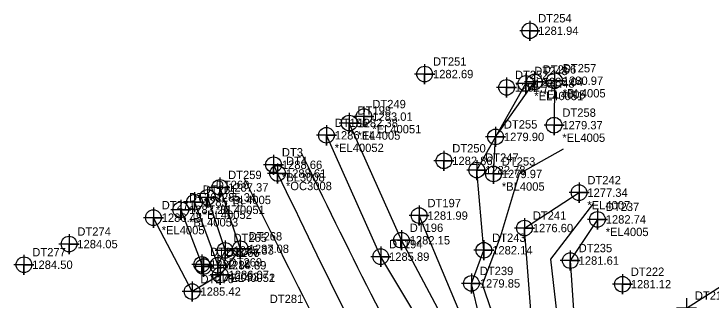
# Model space of a CAD drawing. Extents: x 1394009 to 1394411, y 957864 to 958364.
# Drawn here: x 1394009 to 1394217.7, y 958278.5 to 958364.2 of the extents above; entities that cross this region are included whole.
import ezdxf

# ---------------------------------------------------------------- set-up
doc = ezdxf.new("R2010")
doc.units = 0
for name, color, linetype in [('Exist DTM Breakline', 7, 'Continuous'), ('Exist DTM Breakline Cogo Comment', 7, 'Continuous'), ('Exist DTM Breakline Cogo Elevation', 7, 'Continuous'), ('Exist DTM Breakline Cogo Number', 7, 'Continuous'), ('Exist DTM Breakline Cogo Point CELL', 7, 'Continuous'), ('Exist DTM Breakline Underwater', 7, 'Continuous'), ('Exist DTM Breakline Underwater Cogo Comment', 7, 'Continuous'), ('Exist DTM Breakline Underwater Cogo Elevation', 7, 'Continuous'), ('Exist DTM Breakline Underwater Cogo Number', 7, 'Continuous'), ('Exist DTM Breakline Underwater Cogo Point CELL', 7, 'Continuous'), ('Exist DTM Crownline', 7, 'Continuous'), ('Exist DTM Regular Point Cogo Elevation', 7, 'Continuous'), ('Exist Hydro Stream or Body of Water', 7, 'Continuous'), ('Exist Roads EOP', 7, 'Continuous'), ('Exist Structure Minor Culvert Topo', 7, 'Continuous'), ('Exist Structure Minor Culvert Topo Terminator', 7, 'Continuous'), ('Exist Structure Minor Footbridge', 7, 'Continuous'), ('Exist Structure Minor Footbridge Terminator', 7, 'Continuous'), ('PH Exist DTM NCFMP LIDAR Elevation Point', 7, 'Continuous'), ('Raster_Level_0', 7, 'Continuous')]:
    doc.layers.add(name, color=color, linetype=linetype)

msp = doc.modelspace()

# ---------------------------------------------------------------- linework, layer by layer
at = {"layer": 'Exist DTM Breakline'}
for p, q in [((1394170.8481, 958344.1785), (1394170.7186, 958330.8718)), ((1394063.042, 958307.812), (1394069.9899, 958288.935)), ((1394058.9162, 958305.5481), (1394065.2064, 958289.1828))]:
    msp.add_line(p, q, dxfattribs=at)
for points in [[(1394242.4363, 958236.4587), (1394250.3213, 958249.8392), (1394247.4683, 958258.6227), (1394226.1736, 958256.7484), (1394200.4578, 958246.4971), (1394175.9465, 958237.5482), (1394166.0162, 958243.1539), (1394150.9651, 958262.3435), (1394145.9876, 958283.4911), (1394149.6991, 958293.4183), (1394147.595, 958317.4165), (1394162.2974, 958343.3573)], [(1394153.8085, 958328.2238), (1394164.8354, 958343.8094)], [(1394201.5002, 958152.1258), (1394182.2949, 958191.1856), (1394144.2973, 958260.2559), (1394124.9997, 958296.4083), (1394109.3726, 958331.5215)], [(1394190.4005, 958148.8159), (1394191.5413, 958156.6052), (1394176.0985, 958186.3137), (1394153.7403, 958228.0077), (1394140.0661, 958255.9875), (1394118.8047, 958291.5046), (1394102.5433, 958327.8357)], [(1394152.5846, 958316.2619), (1394153.1879, 958327.1812)], [(1394070.6172, 958312.2397), (1394076.7621, 958293.8578), (1394070.7535, 958286.0492), (1394062.3328, 958281.0618), (1394050.726, 958303.1803)], [(1394066.9181, 958309.2642), (1394072.2129, 958293.3836), (1394069.9934, 958288.9301)], [(1394203.3254, 958156.4773), (1394188.2939, 958197.0575), (1394161.6676, 958234.367), (1394146.9232, 958264.2671), (1394130.3208, 958303.8046)], [(1394183.7059, 958302.6672), (1394175.5913, 958290.3266), (1394176.7902, 958272.6343), (1394192.7029, 958271.0839), (1394210.3962, 958276.1116), (1394227.7375, 958287.1282), (1394241.3942, 958284.8435), (1394266.8472, 958274.7526), (1394273.951, 958265.5798), (1394280.4133, 958252.6154), (1394279.4205, 958214.8325), (1394286.3541, 958194.8367), (1394283.5006, 958151.7161)]]:
    msp.add_lwpolyline(points, dxfattribs=at)
at = {"layer": 'Exist DTM Breakline Cogo Point CELL'}
for points in [[(1394162.2974, 958346.3573), (1394162.2974, 958340.3573), (1394162.2974, 958343.3573), (1394165.2974, 958343.3573), (1394159.2974, 958343.3573)], [(1394164.8354, 958346.8094), (1394164.8354, 958340.8094), (1394164.8354, 958343.8094), (1394167.8354, 958343.8094), (1394161.8354, 958343.8094)], [(1394170.8481, 958347.1785), (1394170.8481, 958341.1785), (1394170.8481, 958344.1785), (1394173.8481, 958344.1785), (1394167.8481, 958344.1785)], [(1394113.7962, 958336.4391), (1394113.7962, 958330.4391), (1394113.7962, 958333.4391), (1394116.7962, 958333.4391), (1394110.7962, 958333.4391)], [(1394109.3726, 958334.5215), (1394109.3726, 958328.5215), (1394109.3726, 958331.5215), (1394112.3726, 958331.5215), (1394106.3726, 958331.5215)], [(1394170.7186, 958333.8718), (1394170.7186, 958327.8718), (1394170.7186, 958330.8718), (1394173.7186, 958330.8718), (1394167.7186, 958330.8718)], [(1394102.5433, 958330.8357), (1394102.5433, 958324.8357), (1394102.5433, 958327.8357), (1394105.5433, 958327.8357), (1394099.5433, 958327.8357)], [(1394153.1978, 958330.3606), (1394153.1978, 958324.3606), (1394153.1978, 958327.3606), (1394156.1978, 958327.3606), (1394150.1978, 958327.3606)], [(1394147.595, 958320.4165), (1394147.595, 958314.4165), (1394147.595, 958317.4165), (1394150.595, 958317.4165), (1394144.595, 958317.4165)], [(1394152.5846, 958319.2619), (1394152.5846, 958313.2619), (1394152.5846, 958316.2619), (1394155.5846, 958316.2619), (1394149.5846, 958316.2619)], [(1394070.6172, 958315.2397), (1394070.6172, 958309.2397), (1394070.6172, 958312.2397), (1394073.6172, 958312.2397), (1394067.6172, 958312.2397)], [(1394066.9181, 958312.2642), (1394066.9181, 958306.2642), (1394066.9181, 958309.2642), (1394069.9181, 958309.2642), (1394063.9181, 958309.2642)], [(1394063.042, 958310.812), (1394063.042, 958304.812), (1394063.042, 958307.812), (1394066.042, 958307.812), (1394060.042, 958307.812)], [(1394058.9162, 958308.5481), (1394058.9162, 958302.5481), (1394058.9162, 958305.5481), (1394061.9162, 958305.5481), (1394055.9162, 958305.5481)], [(1394050.726, 958306.1803), (1394050.726, 958300.1803), (1394050.726, 958303.1803), (1394053.726, 958303.1803), (1394047.726, 958303.1803)], [(1394130.3208, 958306.8046), (1394130.3208, 958300.8046), (1394130.3208, 958303.8046), (1394133.3208, 958303.8046), (1394127.3208, 958303.8046)], [(1394183.7059, 958305.6672), (1394183.7059, 958299.6672), (1394183.7059, 958302.6672), (1394186.7059, 958302.6672), (1394180.7059, 958302.6672)], [(1394124.9997, 958299.4083), (1394124.9997, 958293.4083), (1394124.9997, 958296.4083), (1394127.9997, 958296.4083), (1394121.9997, 958296.4083)], [(1394072.2129, 958296.3836), (1394072.2129, 958290.3836), (1394072.2129, 958293.3836), (1394075.2129, 958293.3836), (1394069.2129, 958293.3836)], [(1394076.7621, 958296.8578), (1394076.7621, 958290.8578), (1394076.7621, 958293.8578), (1394079.7621, 958293.8578), (1394073.7621, 958293.8578)], [(1394149.6991, 958296.4183), (1394149.6991, 958290.4183), (1394149.6991, 958293.4183), (1394152.6991, 958293.4183), (1394146.6991, 958293.4183)], [(1394118.8047, 958294.5046), (1394118.8047, 958288.5046), (1394118.8047, 958291.5046), (1394121.8047, 958291.5046), (1394115.8047, 958291.5046)], [(1394175.5913, 958293.3266), (1394175.5913, 958287.3266), (1394175.5913, 958290.3266), (1394178.5913, 958290.3266), (1394172.5913, 958290.3266)], [(1394065.2064, 958292.1828), (1394065.2064, 958286.1828), (1394065.2064, 958289.1828), (1394068.2064, 958289.1828), (1394062.2064, 958289.1828)], [(1394069.9899, 958291.935), (1394069.9899, 958285.935), (1394069.9899, 958288.935), (1394072.9899, 958288.935), (1394066.9899, 958288.935)], [(1394069.9934, 958291.9301), (1394069.9934, 958285.9301), (1394069.9934, 958288.9301), (1394072.9934, 958288.9301), (1394066.9934, 958288.9301)], [(1394070.7535, 958289.0492), (1394070.7535, 958283.0492), (1394070.7535, 958286.0492), (1394073.7535, 958286.0492), (1394067.7535, 958286.0492)], [(1394145.9876, 958286.4911), (1394145.9876, 958280.4911), (1394145.9876, 958283.4911), (1394148.9876, 958283.4911), (1394142.9876, 958283.4911)], [(1394062.3328, 958284.0618), (1394062.3328, 958278.0618), (1394062.3328, 958281.0618), (1394065.3328, 958281.0618), (1394059.3328, 958281.0618)], [(1394210.3962, 958279.1116), (1394210.3962, 958273.1116), (1394210.3962, 958276.1116), (1394213.3962, 958276.1116), (1394207.3962, 958276.1116)]]:
    msp.add_lwpolyline(points, dxfattribs=at)
for centre in [(1394162.2974, 958343.3573), (1394164.8354, 958343.8094), (1394170.8481, 958344.1785), (1394113.7962, 958333.4391), (1394109.3726, 958331.5215), (1394170.7186, 958330.8718), (1394102.5433, 958327.8357), (1394153.1978, 958327.3606), (1394147.595, 958317.4165), (1394152.5846, 958316.2619), (1394070.6172, 958312.2397), (1394063.042, 958307.812), (1394066.9181, 958309.2642), (1394058.9162, 958305.5481), (1394130.3208, 958303.8046), (1394050.726, 958303.1803), (1394183.7059, 958302.6672), (1394124.9997, 958296.4083), (1394072.2129, 958293.3836), (1394076.7621, 958293.8578), (1394149.6991, 958293.4183), (1394118.8047, 958291.5046), (1394065.2064, 958289.1828), (1394069.9899, 958288.935), (1394069.9934, 958288.9301), (1394175.5913, 958290.3266), (1394070.7535, 958286.0492), (1394145.9876, 958283.4911), (1394062.3328, 958281.0618)]:
    msp.add_circle(centre, 2.344, dxfattribs=at)
at = {"layer": 'Exist DTM Breakline Underwater'}
msp.add_lwpolyline([(1394229.3063, 958094.7507), (1394267.6222, 958126.159), (1394273.9153, 958153.4417), (1394270.8807, 958172.7151), (1394257.7841, 958202.8194), (1394247.0365, 958219.368), (1394259.7999, 958250.0935), (1394260.5275, 958261.5147), (1394243.0302, 958273.0023), (1394215.1121, 958260.9873), (1394175.4465, 958249.379), (1394164.3967, 958267.5944), (1394161.8631, 958300.0699), (1394178.2103, 958310.6665)], dxfattribs=at)
at = {"layer": 'Exist DTM Breakline Underwater Cogo Point CELL'}
for points in [[(1394178.2103, 958313.6665), (1394178.2103, 958307.6665), (1394178.2103, 958310.6665), (1394181.2103, 958310.6665), (1394175.2103, 958310.6665)], [(1394161.8631, 958303.0699), (1394161.8631, 958297.0699), (1394161.8631, 958300.0699), (1394164.8631, 958300.0699), (1394158.8631, 958300.0699)]]:
    msp.add_lwpolyline(points, dxfattribs=at)
for centre in [(1394178.2103, 958310.6665), (1394161.8631, 958300.0699)]:
    msp.add_circle(centre, 2.344, dxfattribs=at)
at = {"layer": 'Exist DTM Crownline'}
msp.add_line((1394086.7137, 958319.0127), (1394087.9321, 958316.4176), dxfattribs=at)
msp.add_spline([(1394087.9321, 958316.4176), (1394109.0623, 958273.1922), (1394131.7594, 958230.1822), (1394152.5248, 958192.8438), (1394173.9492, 958155.4634)], degree=3, dxfattribs=at)
at = {"layer": 'Exist Hydro Stream or Body of Water'}
for points in [[(1394221.231, 958104.5797), (1394238.8971, 958116.0346), (1394254.7004, 958129.0614), (1394261.0998, 958155.6228), (1394258.5223, 958177.5159), (1394245.4045, 958205.4301), (1394241.5211, 958222.9502), (1394246.6022, 958237.6666), (1394253.5489, 958252.431), (1394251.9663, 958257.7082), (1394245.398, 958262.4184), (1394226.1093, 958259.8812), (1394198.4822, 958248.5108), (1394177.4215, 958243.2011), (1394168.9777, 958246.0581), (1394155.8669, 958264.1507), (1394149.2709, 958283.1502), (1394154.661, 958297.4554), (1394160.3871, 958316.4078), (1394173.556, 958323.8378)], [(1394231.5705, 958091.2594), (1394270.5171, 958123.5077), (1394277.8383, 958154.0025), (1394278.608, 958197.1243), (1394267.0972, 958226.2539), (1394275.5986, 958257.1902), (1394265.6306, 958269.8313), (1394243.4303, 958275.2121), (1394210.2309, 958270.0539), (1394177.5999, 958260.6264), (1394172.1027, 958270.6648), (1394169.7578, 958290.7959), (1394182.6519, 958307.5361)]]:
    msp.add_lwpolyline(points, dxfattribs=at)
at = {"layer": 'Exist Roads EOP'}
for p, q in [((1394094.8972, 958322.8354), (1394096.2145, 958320.2223)), ((1394077.957, 958314.8579), (1394078.897, 958312.8974))]:
    msp.add_line(p, q, dxfattribs=at)
for points in [[(1394096.2145, 958320.2223), (1394117.2204, 958277.6897), (1394140.0936, 958234.4745), (1394160.6957, 958197.1466), (1394182.7363, 958159.1242)], [(1394078.897, 958312.8974), (1394101.0229, 958268.6968), (1394123.3315, 958225.72), (1394144.2526, 958188.5895), (1394165.818, 958150.9033)]]:
    msp.add_spline(points, degree=3, dxfattribs=at)
at = {"layer": 'Exist Structure Minor Culvert Topo Terminator'}
for points in [[(1394086.7137, 958322.0127), (1394086.7137, 958316.0127), (1394086.7137, 958319.0127), (1394089.7137, 958319.0127), (1394083.7137, 958319.0127)], [(1394087.9321, 958319.4176), (1394087.9321, 958313.4176), (1394087.9321, 958316.4176), (1394090.9321, 958316.4176), (1394084.9321, 958316.4176)]]:
    msp.add_lwpolyline(points, dxfattribs=at)
for centre in [(1394086.7137, 958319.0127), (1394087.9321, 958316.4176)]:
    msp.add_circle(centre, 2.344, dxfattribs=at)
at = {"layer": 'PH Exist DTM NCFMP LIDAR Elevation Point'}
for points in [[(1394163.4711, 958362.1342), (1394163.4711, 958356.1342), (1394163.4711, 958359.1342), (1394166.4711, 958359.1342), (1394160.4711, 958359.1342)], [(1394131.9735, 958349.1769), (1394131.9735, 958343.1769), (1394131.9735, 958346.1769), (1394134.9735, 958346.1769), (1394128.9735, 958346.1769)], [(1394156.5103, 958345.175), (1394156.5103, 958339.175), (1394156.5103, 958342.175), (1394159.5103, 958342.175), (1394153.5103, 958342.175)], [(1394137.7358, 958323.1974), (1394137.7358, 958317.1974), (1394137.7358, 958320.1974), (1394140.7358, 958320.1974), (1394134.7358, 958320.1974)], [(1394025.4625, 958298.2779), (1394025.4625, 958292.2779), (1394025.4625, 958295.2779), (1394028.4625, 958295.2779), (1394022.4625, 958295.2779)], [(1394011.9701, 958292.0925), (1394011.9701, 958286.0925), (1394011.9701, 958289.0925), (1394014.9701, 958289.0925), (1394008.9701, 958289.0925)], [(1394065.7235, 958291.5141), (1394065.7235, 958285.5141), (1394065.7235, 958288.5141), (1394068.7235, 958288.5141), (1394062.7235, 958288.5141)], [(1394191.2134, 958286.2551), (1394191.2134, 958280.2551), (1394191.2134, 958283.2551), (1394194.2134, 958283.2551), (1394188.2134, 958283.2551)]]:
    msp.add_lwpolyline(points, dxfattribs=at)
for centre in [(1394163.4711, 958359.1342), (1394131.9735, 958346.1769), (1394156.5103, 958342.175), (1394137.7358, 958320.1974), (1394025.4625, 958295.2779), (1394011.9701, 958289.0925), (1394065.7235, 958288.5141), (1394191.2134, 958283.2551)]:
    msp.add_circle(centre, 2.344, dxfattribs=at)

# ---------------------------------------------------------------- texts
at = {"layer": 'Exist DTM Breakline Cogo Comment'}
for s, p in [('*EL4005', (1394167.3354, 958338.8094)), ('*BL4005', (1394173.3481, 958339.1785)), ('*EL40051', (1394164.7974, 958338.3573)), ('*EL40051', (1394116.2962, 958328.4391)), ('*EL4005', (1394111.8726, 958326.5215)), ('*EL4005', (1394173.2186, 958325.8718)), ('*EL40052', (1394105.0433, 958322.8357)), ('*BL4005', (1394155.0846, 958311.2619)), ('*BL4005', (1394073.1172, 958307.2397)), ('*BL40051', (1394069.4181, 958304.2642)), ('*BL40052', (1394065.542, 958302.812)), ('*BL40053', (1394061.4162, 958300.5481)), ('*EL4005', (1394053.226, 958298.1803)), ('*EL4005', (1394186.2059, 958297.6672)), ('*EL40053', (1394067.7064, 958284.1828)), ('*EL40052', (1394072.4899, 958283.935)), ('*EL40051', (1394072.4934, 958283.9301))]:
    msp.add_text(s, height=2.5, dxfattribs=at).set_placement(p)
at = {"layer": 'Exist DTM Breakline Cogo Elevation'}
for s, p in [('1280.97', (1394173.3481, 958342.9285)), ('1281.48', (1394164.7974, 958342.1073)), ('1280.04', (1394167.3354, 958342.5594)), ('1282.38', (1394111.8726, 958330.2715)), ('1283.01', (1394116.2962, 958332.1891)), ('1279.37', (1394173.2186, 958329.6218)), ('1286.14', (1394105.0433, 958326.5857)), ('1279.90', (1394155.6978, 958326.1106)), ('1282.78', (1394150.095, 958316.1665)), ('1279.97', (1394155.0846, 958315.0119)), ('1287.37', (1394073.1172, 958310.9897)), ('1285.34', (1394069.4181, 958308.0142)), ('1285.13', (1394065.542, 958306.562)), ('1283.26', (1394061.4162, 958304.2981)), ('1286.48', (1394053.226, 958301.9303)), ('1281.99', (1394132.8208, 958302.5546)), ('1282.74', (1394186.2059, 958301.4172)), ('1282.15', (1394127.4997, 958295.1583)), ('1285.33', (1394074.7129, 958292.1336)), ('1287.08', (1394079.2621, 958292.6078)), ('1282.14', (1394152.1991, 958292.1683)), ('1285.89', (1394121.3047, 958290.2546)), ('1281.61', (1394178.0913, 958289.0766)), ('1282.18', (1394067.7064, 958287.9328)), ('1284.89', (1394072.4899, 958287.685)), ('1284.89', (1394072.4934, 958287.6801)), ('1286.07', (1394073.2535, 958284.7992)), ('1279.85', (1394148.4876, 958282.2411)), ('1285.42', (1394064.8328, 958279.8118))]:
    msp.add_text(s, height=2.5, dxfattribs=at).set_placement(p)
at = {"layer": 'Exist DTM Breakline Cogo Number'}
for s, p in [('DT248', (1394164.7974, 958345.8573)), ('DT256', (1394167.3354, 958346.3094)), ('DT257', (1394173.3481, 958346.6785)), ('DT249', (1394116.2962, 958335.9391)), ('DT198', (1394111.8726, 958334.0215)), ('DT258', (1394173.2186, 958333.3718)), ('DT195', (1394105.0433, 958330.3357)), ('DT255', (1394155.6978, 958329.8606)), ('DT247', (1394150.095, 958319.9165)), ('DT253', (1394155.0846, 958318.7619)), ('DT259', (1394073.1172, 958314.7397)), ('DT260', (1394069.4181, 958311.7642)), ('DT261', (1394065.542, 958310.312)), ('DT262', (1394061.4162, 958308.0481)), ('DT271', (1394053.226, 958305.6803)), ('DT197', (1394132.8208, 958306.3046)), ('DT237', (1394186.2059, 958305.1672)), ('DT196', (1394127.4997, 958298.9083)), ('DT265', (1394074.7129, 958295.8836)), ('DT268', (1394079.2621, 958296.3578)), ('DT243', (1394152.1991, 958295.9183)), ('DT194', (1394121.3047, 958294.0046)), ('DT235', (1394178.0913, 958292.8266)), ('DT263', (1394067.7064, 958291.6828)), ('DT267', (1394072.4899, 958291.435)), ('DT266', (1394072.4934, 958291.4301)), ('DT269', (1394073.2535, 958288.5492)), ('DT239', (1394148.4876, 958285.9911)), ('DT270', (1394064.8328, 958283.5618)), ('DT216', (1394212.8962, 958278.6116)), ('DT281', (1394085.5781, 958277.6225))]:
    msp.add_text(s, height=2.5, dxfattribs=at).set_placement(p)
at = {"layer": 'Exist DTM Breakline Underwater Cogo Comment'}
msp.add_text('*EL4007', height=2.5, dxfattribs=at).set_placement((1394180.7103, 958305.6665))
at = {"layer": 'Exist DTM Breakline Underwater Cogo Elevation'}
for s, p in [('1277.34', (1394180.7103, 958309.4165)), ('1276.60', (1394164.3631, 958298.8199))]:
    msp.add_text(s, height=2.5, dxfattribs=at).set_placement(p)
at = {"layer": 'Exist DTM Breakline Underwater Cogo Number'}
for s, p in [('DT242', (1394180.7103, 958313.1665)), ('DT241', (1394164.3631, 958302.5699))]:
    msp.add_text(s, height=2.5, dxfattribs=at).set_placement(p)
at = {"layer": 'Exist DTM Regular Point Cogo Elevation'}
for s, p in [('1281.94', (1394165.9711, 958357.8842)), ('1282.69', (1394134.4735, 958344.9269)), ('1281.77', (1394159.0103, 958340.925)), ('1282.86', (1394140.2358, 958318.9474)), ('1284.05', (1394027.9625, 958294.0279)), ('1284.50', (1394014.4701, 958287.8425)), ('1281.12', (1394193.7134, 958282.0051))]:
    msp.add_text(s, height=2.5, dxfattribs=at).set_placement(p)
at = {"layer": 'Exist Structure Minor Culvert Topo'}
for s, p in [('DT3', (1394089.2137, 958321.5127)), ('DT4', (1394090.4321, 958318.9176))]:
    msp.add_text(s, height=2.5, dxfattribs=at).set_placement(p)
at = {"layer": 'Exist Structure Minor Footbridge'}
for s, p in [('*BL3008', (1394089.2137, 958314.0127)), ('*OC3008', (1394090.4321, 958311.4176))]:
    msp.add_text(s, height=2.5, dxfattribs=at).set_placement(p)
at = {"layer": 'Exist Structure Minor Footbridge Terminator'}
for s, p in [('1288.66', (1394089.2137, 958317.7627)), ('1288.61', (1394090.4321, 958315.1676))]:
    msp.add_text(s, height=2.5, dxfattribs=at).set_placement(p)
at = {"layer": 'Raster_Level_0'}
for s, p in [('DT254', (1394165.9711, 958361.6342)), ('DT251', (1394134.4735, 958348.6769)), ('DT252', (1394159.0103, 958344.675)), ('DT250', (1394140.2358, 958322.6974)), ('DT274', (1394027.9625, 958297.7779)), ('DT277', (1394014.4701, 958291.5925)), ('DT222', (1394193.7134, 958285.7551))]:
    msp.add_text(s, height=2.5, dxfattribs=at).set_placement(p)

doc.saveas('drawing.dxf')
